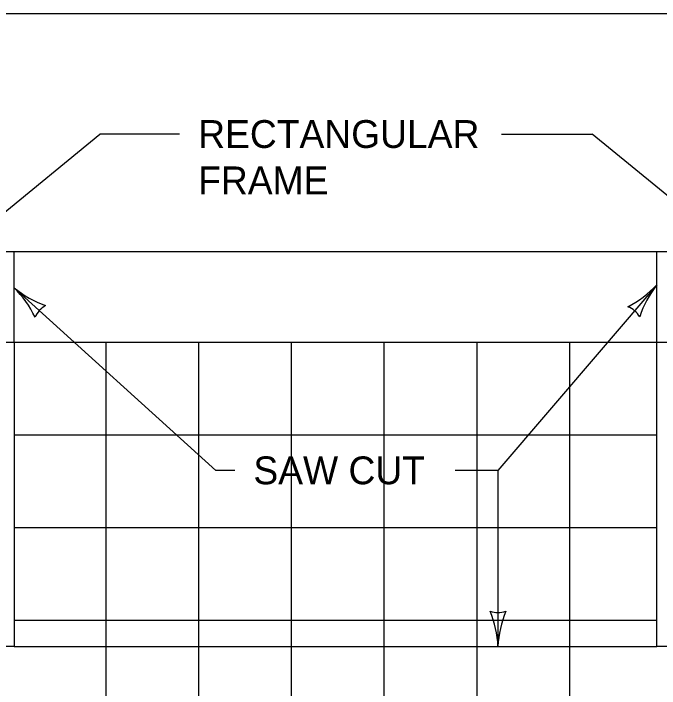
# Model space of a CAD drawing. Extents: x 49991.4 to 50021, y 49987.6 to 50011.4.
# Drawn here: x 50006.932 to 50008.325, y 49997.543 to 49998.999 of the extents above; entities that cross this region are included whole.
import ezdxf

# ---------------------------------------------------------------- set-up
doc = ezdxf.new("R2010")
doc.units = 0
for name, color, linetype in [('Level 1', 7, 'Continuous'), ('Level 2', 7, 'Continuous'), ('Level 3', 7, 'Continuous'), ('Level 4', 7, 'Continuous')]:
    doc.layers.add(name, color=color, linetype=linetype)

msp = doc.modelspace()

# ---------------------------------------------------------------- linework, layer by layer
at = {"layer": 'Level 1'}
for p, q in [((50009.3976, 49998.4848), (50005.5581, 49998.4848)), ((50006.933, 49998.2898), (50006.933, 49998.4848)), ((50008.3187, 49998.2898), (50008.3187, 49998.4848)), ((50009.3976, 49998.2898), (50005.5581, 49998.2898)), ((50006.933, 49998.2898), (50006.933, 49997.6337)), ((50008.3187, 49997.6337), (50008.3187, 49998.2898)), ((50006.933, 49997.6337), (50006.153, 49997.6337)), ((50006.933, 49997.6337), (50008.3187, 49997.6337)), ((50009.0987, 49997.6337), (50008.3187, 49997.6337))]:
    msp.add_line(p, q, dxfattribs=at)
msp.add_lwpolyline([(49999.3835, 49998.9992), (50016.7501, 49998.9992), (50016.7501, 49987.7988), (49999.3835, 49987.7988)], close=True, dxfattribs=at)
at = {"layer": 'Level 2'}
for p, q in [((50006.543, 49998.2673), (50007.118, 49998.7392)), ((50007.29, 49998.7392), (50007.118, 49998.7392)), ((50007.9842, 49998.7392), (50008.1793, 49998.7392)), ((50008.7543, 49998.2673), (50008.1793, 49998.7392)), ((50008.3187, 49998.4136), (50007.9763, 49998.0137)), ((50006.933, 49998.4077), (50007.3683, 49998.0137)), ((50007.409, 49998.0137), (50007.3683, 49998.0137)), ((50007.9763, 49998.0137), (50007.8842, 49998.0137)), ((50007.9763, 49998.0137), (50007.9763, 49997.6337))]:
    msp.add_line(p, q, dxfattribs=at)
at = {"layer": 'Level 3'}
for centre, radius, start, end in [((50008.1494, 49998.5737), 0.233, 297.3576, 316.6075), ((50008.4934, 49998.2761), 0.2223, 141.7953, 161.9788), ((50006.7772, 49998.2491), 0.2223, 25.3091, 45.4926), ((50007.0807, 49998.5879), 0.233, 230.6804, 249.9303), ((50007.0281, 49998.3216), 0.0548, 119.9919, 155.7143), ((50008.2353, 49998.3162), 0.0548, 31.5736, 67.296), ((50007.7542, 49997.6246), 0.2223, 2.3605, 22.544), ((50007.9763, 49997.7619), 0.0548, 252.1388, 287.8612), ((50008.209, 49997.6222), 0.233, 157.9228, 177.1727)]:
    msp.add_arc(centre, radius, start, end, dxfattribs=at)
at = {"layer": 'Level 4'}
for p, q in [((50007.1305, 49998.2898), (50007.1305, 49996.8898)), ((50007.3305, 49998.2898), (50007.3305, 49996.8898)), ((50007.5305, 49998.2898), (50007.5305, 49996.8898)), ((50007.7305, 49998.2898), (50007.7305, 49996.8898)), ((50007.9305, 49998.2898), (50007.9305, 49996.8898)), ((50008.1305, 49998.2898), (50008.1305, 49996.8898)), ((50008.3187, 49998.0898), (50006.933, 49998.0898)), ((50008.3187, 49997.8898), (50006.933, 49997.8898)), ((50008.3187, 49997.6898), (50006.933, 49997.6898))]:
    msp.add_line(p, q, dxfattribs=at)

# ---------------------------------------------------------------- texts
at = {"layer": 'Level 2'}
for s, p in [('RECTANGULAR', (50007.33, 49998.7092)), ('FRAME', (50007.33, 49998.6092)), ('SAW CUT', (50007.449, 49997.9837))]:
    msp.add_text(s, height=0.06, dxfattribs=at).set_placement(p)

doc.saveas('drawing.dxf')
